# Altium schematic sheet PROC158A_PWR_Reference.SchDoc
size 431 x 279 mm; Date: Not shown in title block; ApprovedBy: Not shown in title block; CheckedBy: Not shown in title block; Author: Not shown in title block; CompanyName: Not shown in title block; Engineer: Not shown in title block; Organization: Not shown in title block; Address1: Not shown in title block; Address2: Not shown in title block; Address3: Not shown in title block; Address4: Not shown in title block; DocumentNumber: 3; Revision: Use project parameter SCH_Rev; SheetNumber: 3; SheetTotal: 24; PageSetup: Record=PageOptions¦CenterHorizontal=True¦CenterVertical=True¦PrintScale=1.00¦XCorrection=1.00¦YCorrection=1.00¦PrintKind=0¦BorderSize=5000000¦LeftOffset=0¦BottomOffset=0¦Orientation=2¦PaperLength=1000¦PaperWidth=1000¦Scale=100¦PaperSource=15¦PrintQuality=600¦MediaType=1¦DitherType=10¦PaperKind=Letter¦PrintScaleMode=1
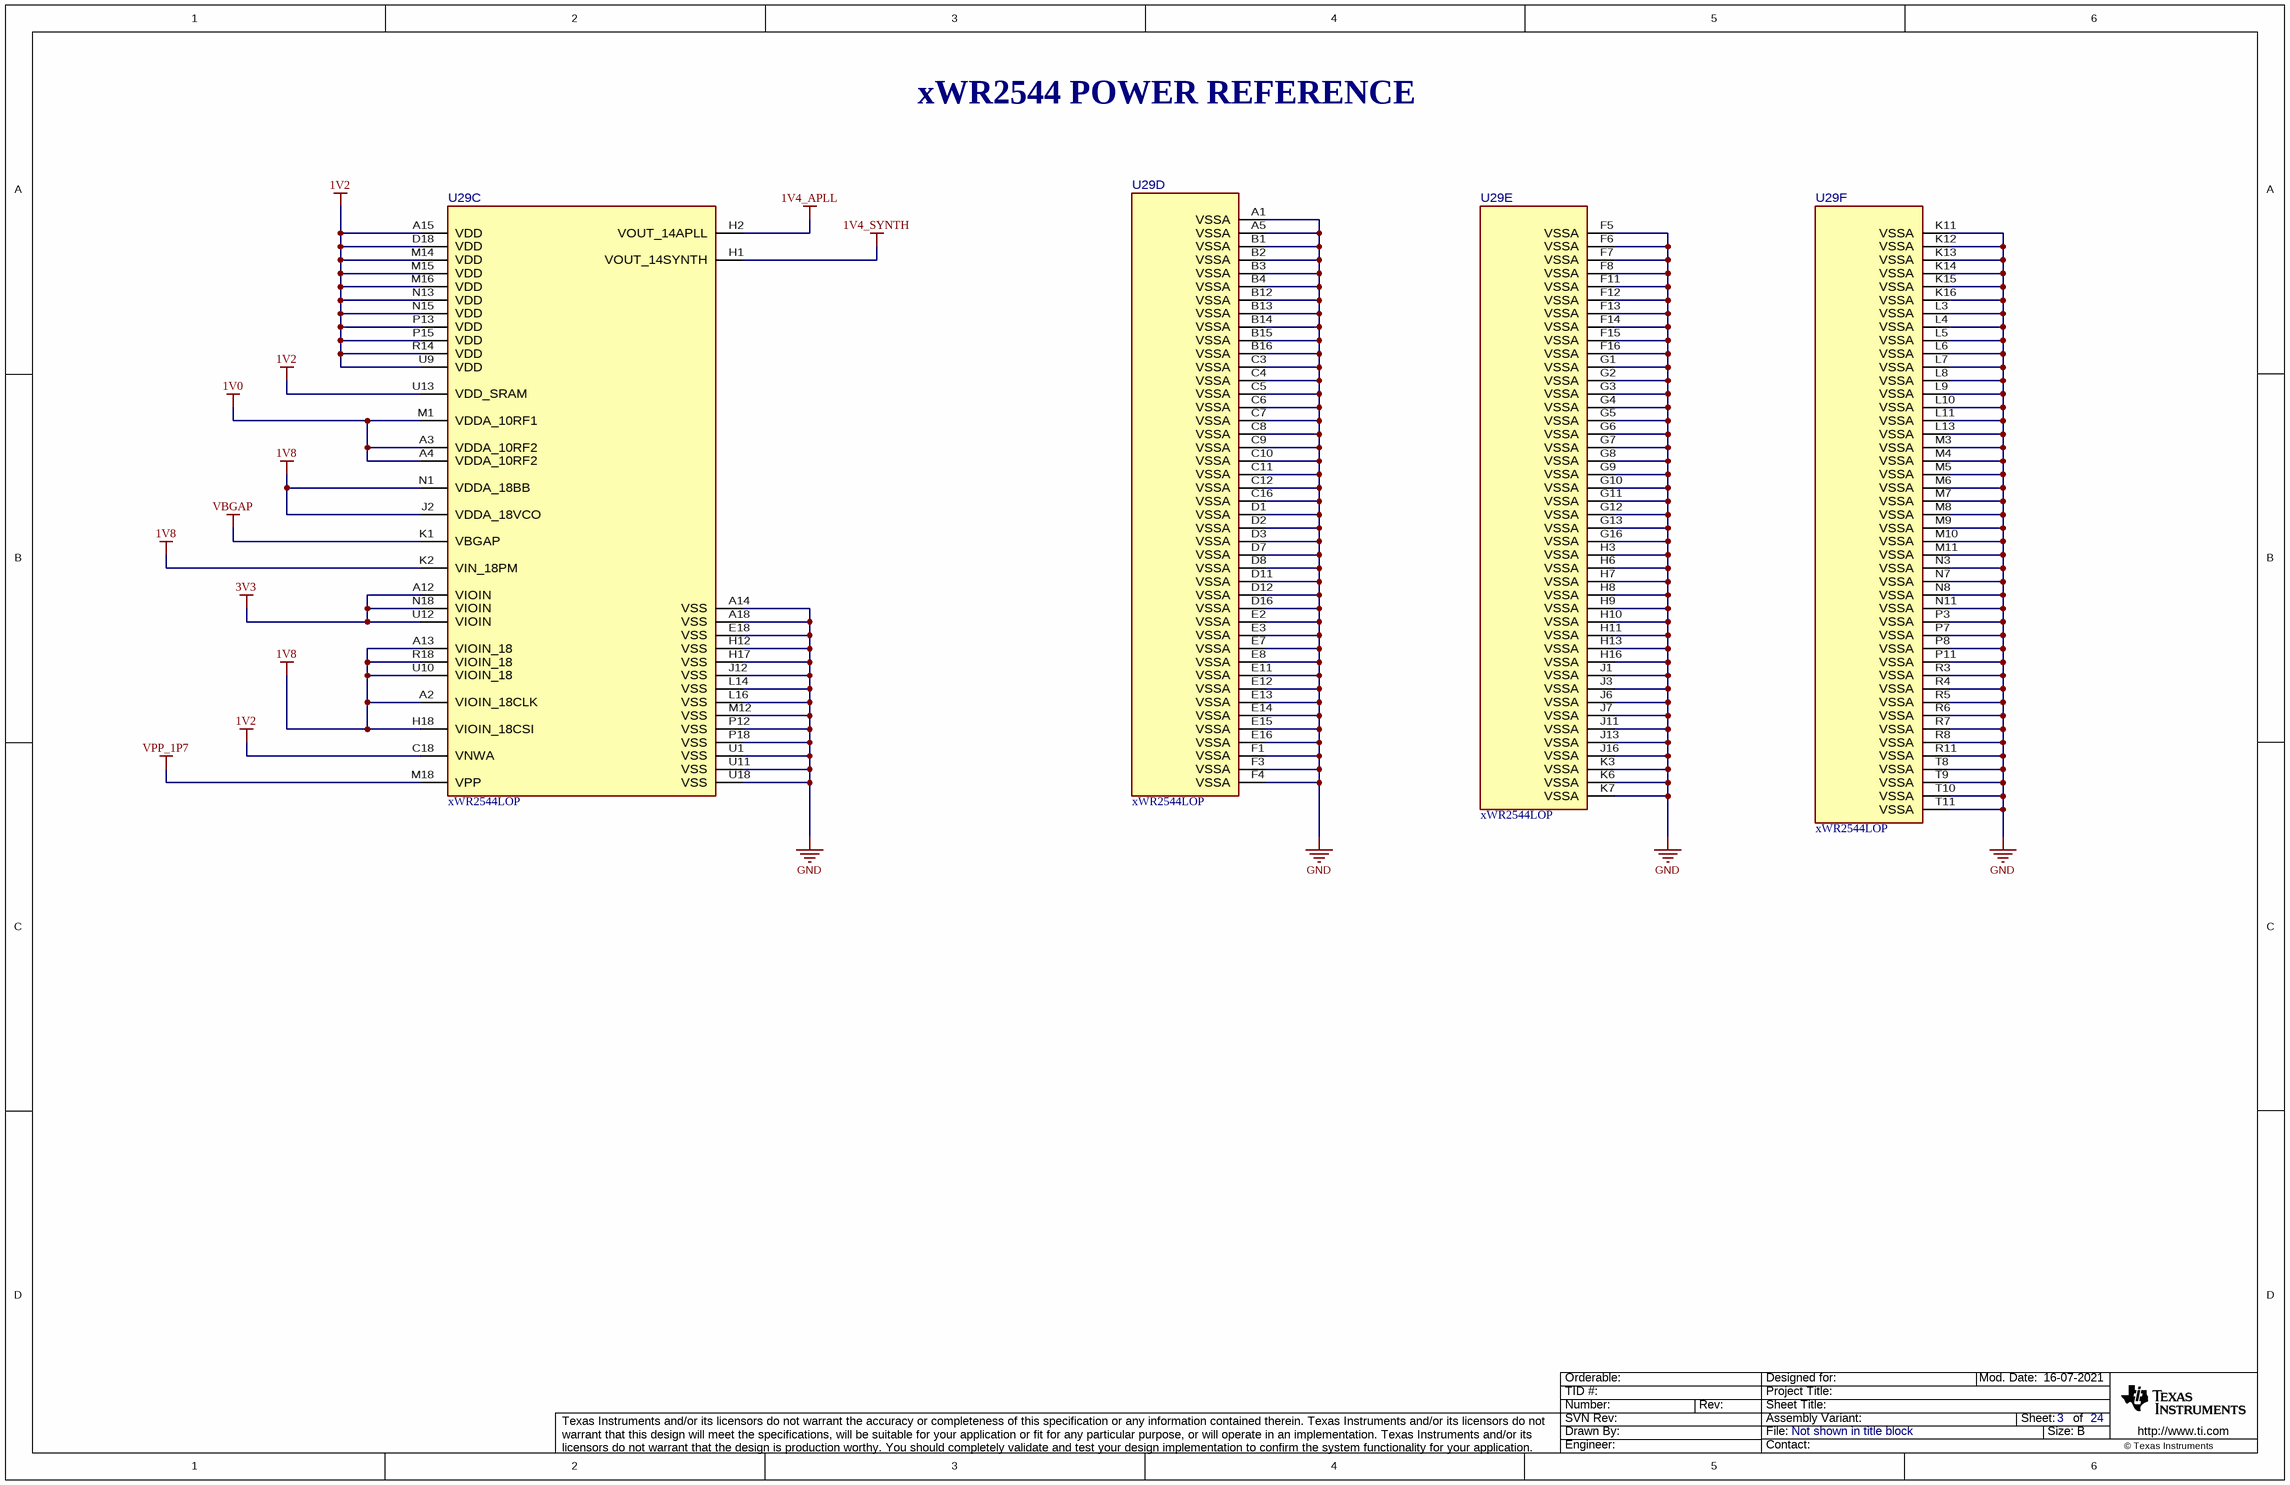
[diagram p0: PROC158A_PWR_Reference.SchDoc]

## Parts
U29  xWR2544LOP  [0-IPC_C]  (parts C,D,E,F of 6)

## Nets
1V0: U29.A3(VDDA_10RF2) U29.A4(VDDA_10RF2) U29.M1(VDDA_10RF1)
1V2: U29.A15(VDD) U29.C18(VNWA) U29.D18(VDD) U29.M14(VDD) U29.M15(VDD) U29.M16(VDD) U29.N13(VDD) U29.N15(VDD) U29.P13(VDD) U29.P15(VDD) U29.R14(VDD) U29.U9(VDD) U29.U13(VDD_SRAM)
1V4_APLL: U29.H2(VOUT_14APLL)
1V4_SYNTH: U29.H1(VOUT_14SYNTH)
1V8: U29.A2(VIOIN_18CLK) U29.A13(VIOIN_18) U29.H18(VIOIN_18CSI) U29.J2(VDDA_18VCO) U29.K2(VIN_18PM) U29.N1(VDDA_18BB) U29.R18(VIOIN_18) U29.U10(VIOIN_18)
3V3: U29.A12(VIOIN) U29.N18(VIOIN) U29.U12(VIOIN)
GND: U29.A1(VSSA) U29.A5(VSSA) U29.A14(VSS) U29.A18(VSS) U29.B1(VSSA) U29.B2(VSSA) U29.B3(VSSA) U29.B4(VSSA) U29.B12(VSSA) U29.B13(VSSA) U29.B14(VSSA) U29.B15(VSSA) U29.B16(VSSA) U29.C3(VSSA) U29.C4(VSSA) U29.C5(VSSA) U29.C6(VSSA) U29.C7(VSSA) U29.C8(VSSA) U29.C9(VSSA) U29.C10(VSSA) U29.C11(VSSA) U29.C12(VSSA) U29.C16(VSSA) U29.D1(VSSA) U29.D2(VSSA) U29.D3(VSSA) U29.D7(VSSA) U29.D8(VSSA) U29.D11(VSSA) U29.D12(VSSA) U29.D16(VSSA) U29.E2(VSSA) U29.E3(VSSA) U29.E7(VSSA) U29.E8(VSSA) U29.E11(VSSA) U29.E12(VSSA) U29.E13(VSSA) U29.E14(VSSA) U29.E15(VSSA) U29.E16(VSSA) U29.E18(VSS) U29.F1(VSSA) U29.F3(VSSA) U29.F4(VSSA) U29.F5(VSSA) U29.F6(VSSA) U29.F7(VSSA) U29.F8(VSSA) U29.F11(VSSA) U29.F12(VSSA) U29.F13(VSSA) U29.F14(VSSA) U29.F15(VSSA) U29.F16(VSSA) U29.G1(VSSA) U29.G2(VSSA) U29.G3(VSSA) U29.G4(VSSA) U29.G5(VSSA) U29.G6(VSSA) U29.G7(VSSA) U29.G8(VSSA) U29.G9(VSSA) U29.G10(VSSA) U29.G11(VSSA) U29.G12(VSSA) U29.G13(VSSA) U29.G16(VSSA) U29.H3(VSSA) U29.H6(VSSA) U29.H7(VSSA) U29.H8(VSSA) U29.H9(VSSA) U29.H10(VSSA) U29.H11(VSSA) U29.H12(VSS) U29.H13(VSSA) U29.H16(VSSA) U29.H17(VSS) U29.J1(VSSA) U29.J3(VSSA) U29.J6(VSSA) U29.J7(VSSA) U29.J11(VSSA) U29.J12(VSS) U29.J13(VSSA) U29.J16(VSSA) U29.K3(VSSA) U29.K6(VSSA) U29.K7(VSSA) U29.K11(VSSA) U29.K12(VSSA) U29.K13(VSSA) U29.K14(VSSA) U29.K15(VSSA) U29.K16(VSSA) U29.L3(VSSA) U29.L4(VSSA) U29.L5(VSSA) U29.L6(VSSA) U29.L7(VSSA) U29.L8(VSSA) U29.L9(VSSA) U29.L10(VSSA) U29.L11(VSSA) U29.L13(VSSA) U29.L14(VSS) U29.L16(VSS) U29.M3(VSSA) U29.M4(VSSA) U29.M5(VSSA) U29.M6(VSSA) U29.M7(VSSA) U29.M8(VSSA) U29.M9(VSSA) U29.M10(VSSA) U29.M11(VSSA) U29.M12(VSS) U29.N3(VSSA) U29.N7(VSSA) U29.N8(VSSA) U29.N11(VSSA) U29.P3(VSSA) U29.P7(VSSA) U29.P8(VSSA) U29.P11(VSSA) U29.P12(VSS) U29.P18(VSS) U29.R3(VSSA) U29.R4(VSSA) U29.R5(VSSA) U29.R6(VSSA) U29.R7(VSSA) U29.R8(VSSA) U29.R11(VSSA) U29.T8(VSSA) U29.T9(VSSA) U29.T10(VSSA) U29.T11(VSSA) U29.U1(VSS) U29.U11(VSS) U29.U18(VSS)
VBGAP: U29.K1(VBGAP)
VPP_1P7: U29.M18(VPP)

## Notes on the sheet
- xWR2544 POWER REFERENCE

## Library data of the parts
U29 = CMP-0098489-4: Manufacturer: Texas Instruments; SizeZ_mm: 1.234mm; Standoff Height: 0.216mm; AEC Category: Q200; CompType: IC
